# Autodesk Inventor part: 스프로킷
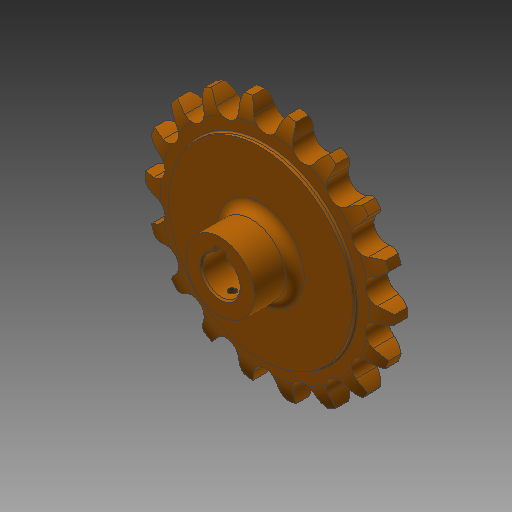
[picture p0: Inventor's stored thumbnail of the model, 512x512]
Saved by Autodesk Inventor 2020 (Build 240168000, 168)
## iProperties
Created: 2016-03
Part Number: 스프로킷
Material: 강철, 탄소
Document SubType Name: Modeling
Designer: mduedu
Density: 7.87 g/cm^3
Mass: 301.849 g
Surface Area: 124.883 cm^2
Volume: 38.3544 cm^3
Appearance: 반광택
Author: mduedu
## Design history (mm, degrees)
sketch "스케치1"
  geometry: L1 (0, 5)-(29.5, 5); L2 (29.5, 5)-(29.5, 4.1); L3 (30, 3.6)-(33.625, 3.6); L4 (40, 2)-(40, 0); L5 (40, 0)-(0, 0); L6 (0, 0)-(0, 5); L7 (0, -5)-(29.5, -5); L8 (29.5, -5)-(29.5, -4.1); L9 (30, -3.6)-(33.625, -3.6); L10 (40, -2)-(40, 0); L11 (0, 0)-(0, -5); A1 r 13.5 centre (33.625, -9.9) between (40, 2) and (33.625, 3.6); A2 r 13.5 centre (33.625, 9.9) between (33.625, -3.6) and (40, -2); A3 r 0.5 centre (30, 4.1) between (29.5, 4.1) and (30, 3.6); A4 r 0.5 centre (30, -4.1) between (30, -3.6) and (29.5, -4.1); 2 further points
  constraints: 22 end point, 8 point on circle, 6 symmetric about line, 5 tangent, 4 centre point, 4 parallel, 4 point on line, 1 equal radius, 1 horizontal, 1 perpendicular, 1 other
  dimensions: "d0" = 80 diameter of L4 L6; "d2" = 59 diameter of L2 L6; "d3" = 1.6 vertical distance of L4.start L3.end; "d4" = 3.6 distance from line of L4.end L3; "d5" = 5 distance between parallel lines of L5 L1; "d6" = 13.5 radius of A1; "d15" = 0.5 radius of A3
revolve "회전1" sketch "스케치1" stored, may be unused: angle "d7" = 90 deg
sketch "스케치2" dims "d8" = 65.2, "d11" = 80
  geometry: L1 (0, 0)-(0, 32.6); A1 r 36.57 centre (0, 0) between (-16.231, 32.771) and (0, 36.57); A2 r 3.97 centre (0, 36.57) between (-3.866, 35.665) and (0, 32.6); A3 r 12.7 centre (-16.231, 32.771) between (-3.866, 35.665) and (-5.534, 39.615); A4 r 12.7 centre (16.231, 32.771) between (5.534, 39.615) and (3.866, 35.665); A5 r 3.97 centre (0, 36.57) between (0, 32.6) and (3.866, 35.665); A6 r 40 centre (0, 0) between (5.534, 39.615) and (-5.534, 39.615); 2 further points
  constraints: 12 point on circle, 6 centre point, 4 coincident, 3 symmetric about line, 2 end point, 1 point on line, 1 tangent, 1 vertical, 1 vertical alignment, 7 other
  dimensions: "d10" = 73.14 diameter of A1; "d12" = 12.7 radius of A3
extrude "돌출1" cut sketch "스케치2" extent not by distance; stored distance "d13" = 10; taper "d14" = 0 deg
sketch "스케치3"
  geometry: C1 r 11 at (0, 0); 1 further point
  constraints: 1 centre point, 1 coincident
  dimensions: "d19" = 22 diameter of C1
extrude "돌출2" join sketch "스케치3" distance "d20" = 13; taper "d21" = 0 deg
fillet "모깎기1" dims "d22" = 3
sketch "스케치4"
  geometry: L1 (-2, 0)-(2, 0); L2 (2, 0)-(2, 7.8); L3 (2, 7.8)-(-2, 7.8); L4 (-2, 7.8)-(-2, 0); C1 r 6 at (0, 0); 2 further points
  constraints: 8 end point, 2 coincident, 2 parallel, 1 centre point, 1 horizontal, 1 midpoint, 1 perpendicular
  dimensions: "d23" = 12 diameter of C1; "d25" = 4 distance of L2.end L3.end; "d26" = 7.8 distance of L1.end L2.end
extrude "돌출3" cut sketch "스케치4" extent not by distance; stored distance "d27" = 8; taper "d28" = 0 deg
chamfer "모따기1" distance "d29" = 0.5; stored, may be unused: second distance "d30" = 2, angle "d31" = 45 deg
node "작업 평면1"
sketch "스케치5"
  geometry: L1 (11, 13)-(-11, 13) reference; 2 further points
  constraints: 1 vertical alignment
  dimensions: "d32" = 4 distance from line of point (0, 9) L1
hole "구멍1" sketch "스케치5" at (0, 9) diameter "d33" = 2.459; stored, may be unused: countersink angle "d37" = 90 deg, drill point angle "d39" = 118 deg; dims "d34" = 6, "d35" = 4, "d36" = 2, "d38" = 8
node "솔리드1"
pattern_circular "원형 패턴1" dims angle "d17" = 360 deg
